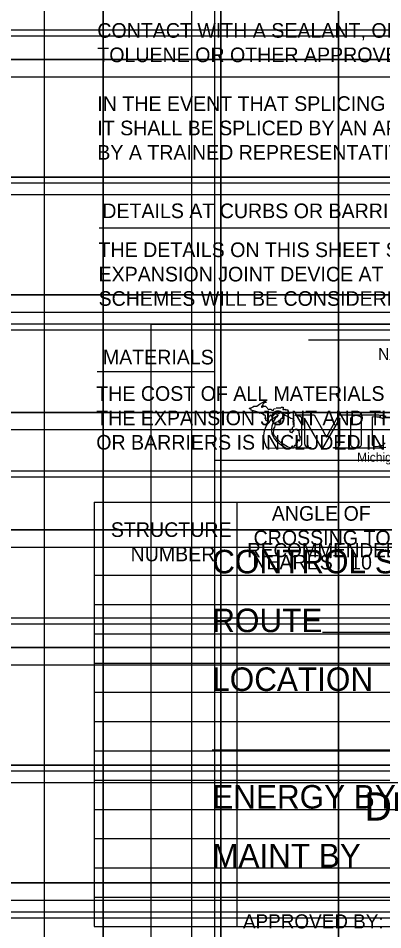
# Model space of a CAD drawing. Extents: x 19590 to 20151, y 19944 to 20103.
# Drawn here: x 20106.58 to 20118.97, y 20023.21 to 20054.22 of the extents above; entities that cross this region are included whole.
import ezdxf

# ---------------------------------------------------------------- set-up
doc = ezdxf.new("R2010")
doc.units = 0
for name, color, linetype in [('DETAIL_TEXT_DIMEN_PR', 7, 'Continuous'), ('Sheet_Border_Block_LightingInventory', 7, 'Continuous'), ('Sheet_Border_PlanOverProf_Grid+Sta+EL_40x', 7, 'Continuous'), ('Sheet_Border_PlanOverProf_Grid+Sta+EL_50x', 7, 'Continuous'), ('Sheet_Border_Prof_Triple_Grid+Sta+EL_40x', 7, 'Continuous'), ('Sheet_Border_Prof_Triple_Grid+Sta+EL_50x', 7, 'Continuous'), ('Sheet_Border_TitleSheet', 7, 'Continuous'), ('Sheet_Border_TitleSheet_ConsultantBlock', 7, 'Continuous'), ('Sheet_Border_XS_Grid', 7, 'Continuous')]:
    doc.layers.add(name, color=color, linetype=linetype)

msp = doc.modelspace()

# ---------------------------------------------------------------- linework, layer by layer
at = {"layer": 'DETAIL_TEXT_DIMEN_PR'}
for p, q in [((20109.339, 20047.087), (20121.031, 20047.087)), ((20109.261, 20042.198), (20113.23, 20042.198)), ((20109.159, 20037.759), (20109.159, 20023.328)), ((20109.159, 20037.759), (20139.598, 20037.759)), ((20114.011, 20037.759), (20114.011, 20035.271)), ((20109.159, 20035.271), (20139.598, 20035.271)), ((20114.011, 20035.271), (20114.011, 20023.348)), ((20109.159, 20034.275), (20139.598, 20034.275)), ((20109.159, 20033.28), (20139.598, 20033.28)), ((20109.159, 20032.285), (20139.598, 20032.285)), ((20109.159, 20031.29), (20139.598, 20031.29)), ((20109.159, 20030.294), (20139.598, 20030.294)), ((20109.159, 20029.299), (20139.598, 20029.299)), ((20109.159, 20028.304), (20139.598, 20028.304)), ((20109.159, 20027.309), (20139.598, 20027.309)), ((20109.159, 20026.314), (20139.598, 20026.314)), ((20109.159, 20025.318), (20139.598, 20025.318)), ((20109.159, 20024.323), (20139.598, 20024.323)), ((20109.159, 20023.328), (20139.598, 20023.328))]:
    msp.add_line(p, q, dxfattribs=at)
at = {"layer": 'Sheet_Border_Block_LightingInventory'}
for p, q in [((20111.107, 20015.013), (20111.107, 20043.813)), ((20111.107, 20043.813), (20143.267, 20043.813)), ((20116.927, 20033.337), (20140.777, 20033.337)), ((20113.177, 20029.337), (20140.777, 20029.337))]:
    msp.add_line(p, q, dxfattribs=at)
for points in [[(20115.345, 20040.961), (20115.504, 20040.961), (20115.532, 20040.99), (20115.59, 20040.99), (20115.59, 20040.961), (20115.576, 20040.904), (20115.633, 20040.904), (20115.648, 20040.918), (20115.662, 20040.904), (20115.676, 20040.904), (20115.676, 20040.889), (20115.72, 20040.904), (20115.748, 20040.875), (20115.748, 20040.832), (20115.763, 20040.832), (20115.792, 20040.803), (20115.792, 20040.788), (20115.82, 20040.788), (20115.82, 20040.774), (20115.691, 20040.774), (20115.662, 20040.788), (20115.648, 20040.788), (20115.633, 20040.76), (20115.648, 20040.745), (20115.633, 20040.731), (20115.619, 20040.731), (20115.604, 20040.76), (20115.59, 20040.774), (20115.518, 20040.788), (20115.475, 20040.803), (20115.46, 20040.788), (20115.446, 20040.76), (20115.374, 20040.745), (20115.345, 20040.76), (20115.316, 20040.76), (20115.273, 20040.731), (20115.244, 20040.688), (20115.23, 20040.688), (20115.23, 20040.702), (20115.244, 20040.716), (20115.259, 20040.745), (20115.23, 20040.731), (20115.216, 20040.731), (20115.201, 20040.716), (20115.172, 20040.688), (20115.158, 20040.731), (20115.144, 20040.702), (20115.115, 20040.673), (20115.086, 20040.63), (20115.028, 20040.529), (20115.014, 20040.529), (20115, 20040.544), (20115, 20040.572), (20115.014, 20040.616), (20115, 20040.616), (20114.985, 20040.601), (20114.971, 20040.616), (20114.985, 20040.63), (20114.985, 20040.702), (20114.971, 20040.716), (20114.928, 20040.716), (20114.928, 20040.731), (20114.913, 20040.745), (20114.928, 20040.745), (20114.913, 20040.76), (20114.884, 20040.76), (20114.856, 20040.774), (20114.827, 20040.803), (20114.812, 20040.774), (20114.784, 20040.803), (20114.769, 20040.803), (20114.74, 20040.817), (20114.654, 20040.846), (20114.496, 20040.889), (20114.496, 20040.904), (20114.467, 20040.932), (20114.467, 20040.947), (20114.438, 20040.947), (20114.582, 20041.004), (20114.582, 20041.019), (20114.697, 20041.019), (20114.74, 20041.062), (20114.784, 20041.091), (20114.884, 20041.148), (20114.942, 20041.177), (20115, 20041.177), (20115.014, 20041.163), (20115, 20041.148), (20114.985, 20041.148), (20114.956, 20041.134), (20114.928, 20041.12), (20114.913, 20041.105), (20114.884, 20041.062), (20114.87, 20041.033), (20114.856, 20041.019), (20114.856, 20040.99), (20114.87, 20040.99), (20114.884, 20041.004), (20114.899, 20041.033), (20114.928, 20041.033), (20114.899, 20041.004)], [(20114.899, 20041.004), (20114.942, 20041.019), (20114.985, 20041.019), (20115.014, 20041.004), (20115.043, 20040.961), (20115.057, 20040.947), (20115.086, 20040.904), (20115.129, 20040.918), (20115.172, 20040.918), (20115.201, 20040.889), (20115.244, 20040.875), (20115.259, 20040.889), (20115.259, 20040.904), (20115.273, 20040.932), (20115.331, 20040.947)], [(20115.921, 20040.529), (20115.921, 20040.5), (20115.921, 20040.486), (20115.95, 20040.472), (20115.95, 20040.342), (20115.936, 20040.313), (20115.921, 20040.313), (20115.907, 20040.299), (20115.892, 20040.27), (20115.892, 20040.241), (20115.878, 20040.227), (20115.835, 20040.227), (20115.82, 20040.212), (20115.82, 20040.155), (20115.835, 20040.14), (20115.878, 20040.126), (20115.907, 20040.126), (20115.907, 20040.169), (20115.921, 20040.169), (20115.95, 20040.198), (20115.95, 20040.212), (20115.936, 20040.212), (20115.993, 20040.227), (20116.036, 20040.256), (20116.065, 20040.241), (20116.08, 20040.212), (20116.123, 20040.198), (20116.123, 20040.126), (20116.137, 20040.097), (20116.137, 20040.025), (20116.166, 20039.968), (20116.166, 20039.953), (20116.152, 20039.953), (20116.152, 20039.881), (20116.123, 20039.838), (20116.108, 20039.881), (20116.094, 20039.881), (20116.08, 20039.867), (20116.08, 20039.838), (20116.065, 20039.809), (20116.065, 20039.78), (20116.022, 20039.78), (20116.022, 20039.737), (20116.008, 20039.694), (20115.993, 20039.68), (20115.979, 20039.68), (20115.964, 20039.651), (20115.95, 20039.636), (20115.95, 20039.593), (20115.878, 20039.593), (20115.82, 20039.608), (20115.734, 20039.636), (20115.532, 20039.766), (20115.432, 20039.852), (20115.374, 20039.896), (20115.345, 20039.953), (20115.302, 20039.996), (20115.273, 20040.054), (20115.259, 20040.097), (20115.259, 20040.14), (20115.273, 20040.184), (20115.273, 20040.212), (20115.259, 20040.256), (20115.288, 20040.27), (20115.302, 20040.313), (20115.331, 20040.4), (20115.316, 20040.414), (20115.331, 20040.428), (20115.345, 20040.472), (20115.36, 20040.486), (20115.403, 20040.5), (20115.417, 20040.486), (20115.432, 20040.529), (20115.46, 20040.558), (20115.446, 20040.5), (20115.446, 20040.457), (20115.475, 20040.486), (20115.489, 20040.486), (20115.46, 20040.443), (20115.489, 20040.472), (20115.504, 20040.5), (20115.504, 20040.587), (20115.518, 20040.601), (20115.532, 20040.601), (20115.547, 20040.616), (20115.604, 20040.616), (20115.604, 20040.616), (20115.576, 20040.616), (20115.561, 20040.644), (20115.576, 20040.673), (20115.576, 20040.702), (20115.59, 20040.716), (20115.648, 20040.716), (20115.676, 20040.702), (20115.72, 20040.688), (20115.734, 20040.688), (20115.763, 20040.673), (20115.777, 20040.659), (20115.849, 20040.616), (20115.936, 20040.587), (20115.95, 20040.515)], [(20115.95, 20040.515), (20115.936, 20040.529)], [(20118.988, 20040.587), (20118.945, 20040.616), (20118.888, 20040.63), (20118.888, 20040.716), (20118.96, 20040.716), (20119.075, 20040.688)], [(20119.075, 20039.622), (20118.931, 20039.593), (20118.888, 20039.593), (20118.888, 20039.68), (20118.916, 20039.68), (20118.974, 20039.694), (20119.06, 20039.78)]]:
    msp.add_lwpolyline(points, dxfattribs=at)
for points in [[(20116.641, 20040.731), (20117.059, 20039.968), (20117.476, 20040.731), (20118.096, 20040.731), (20118.096, 20040.702), (20118.052, 20040.702), (20117.937, 20040.673), (20117.923, 20040.673), (20117.923, 20040.659), (20117.894, 20040.63), (20117.88, 20040.601), (20117.88, 20039.708), (20117.894, 20039.68), (20117.937, 20039.636), (20117.995, 20039.622), (20118.096, 20039.622), (20118.096, 20039.593), (20117.304, 20039.593), (20117.304, 20039.622), (20117.419, 20039.622), (20117.462, 20039.636), (20117.476, 20039.665), (20117.505, 20039.68), (20117.52, 20039.708), (20117.52, 20040.616), (20116.929, 20039.593), (20116.9, 20039.593), (20116.31, 20040.616), (20116.31, 20039.752), (20116.339, 20039.68), (20116.382, 20039.651), (20116.44, 20039.622), (20116.526, 20039.622), (20116.526, 20039.593), (20116.008, 20039.593), (20116.008, 20039.622), (20116.022, 20039.622), (20116.123, 20039.636), (20116.166, 20039.651), (20116.18, 20039.665), (20116.209, 20039.694), (20116.224, 20039.723), (20116.224, 20040.601), (20116.209, 20040.63), (20116.195, 20040.659), (20116.166, 20040.673), (20116.123, 20040.688), (20116.051, 20040.702), (20116.008, 20040.702), (20116.008, 20040.731)], [(20118.844, 20040.644), (20118.772, 20040.644), (20118.614, 20040.659), (20118.614, 20039.708), (20118.628, 20039.694), (20118.657, 20039.665), (20118.744, 20039.651), (20118.83, 20039.665), (20118.888, 20039.68), (20118.888, 20039.593), (20118.038, 20039.593), (20118.038, 20039.622), (20118.139, 20039.622), (20118.182, 20039.636), (20118.225, 20039.665), (20118.24, 20039.68), (20118.254, 20039.708), (20118.254, 20040.601), (20118.24, 20040.63), (20118.225, 20040.659), (20118.096, 20040.702), (20118.038, 20040.702), (20118.038, 20040.731), (20118.844, 20040.731), (20118.888, 20040.716), (20118.888, 20040.63)], [(20115.057, 20039.593), (20115.014, 20039.651), (20114.985, 20039.723), (20114.956, 20039.795), (20114.928, 20039.953), (20114.928, 20040.025), (20114.956, 20040.184), (20115.014, 20040.342), (20115.057, 20040.414), (20115.115, 20040.472), (20115.172, 20040.558), (20115.244, 20040.616), (20115.417, 20040.716), (20115.36, 20040.644), (20115.316, 20040.601), (20115.288, 20040.544), (20115.244, 20040.472), (20115.23, 20040.414), (20115.201, 20040.342), (20115.187, 20040.256), (20115.187, 20040.169), (20115.201, 20040.097), (20115.244, 20039.996), (20115.288, 20039.924), (20115.36, 20039.838), (20115.46, 20039.752), (20115.576, 20039.665), (20115.72, 20039.579)]]:
    msp.add_lwpolyline(points, close=True, dxfattribs=at)
at = {"layer": 'Sheet_Border_PlanOverProf_Grid+Sta+EL_40x'}
for p, q in [((20137.467, 20053.813), (20017.467, 20053.813)), ((20107.467, 20053.813), (20107.467, 20016.413)), ((20112.467, 20053.813), (20112.467, 20016.413)), ((20117.467, 20053.813), (20117.467, 20016.413)), ((20137.467, 20048.813), (20017.467, 20048.813)), ((20137.467, 20043.813), (20017.467, 20043.813)), ((20137.467, 20038.813), (20017.467, 20038.813)), ((20137.467, 20033.813), (20017.467, 20033.813)), ((20137.467, 20028.813), (20017.467, 20028.813)), ((20137.467, 20023.813), (20017.467, 20023.813))]:
    msp.add_line(p, q, dxfattribs=at)
at = {"layer": 'Sheet_Border_PlanOverProf_Grid+Sta+EL_50x'}
for p, q in [((20137.467, 20052.813), (20017.467, 20052.813)), ((20109.467, 20052.813), (20109.467, 20018.413)), ((20113.467, 20052.813), (20113.467, 20018.413)), ((20117.467, 20052.813), (20117.467, 20018.413)), ((20137.467, 20048.813), (20017.467, 20048.813)), ((20137.467, 20044.813), (20017.467, 20044.813)), ((20137.467, 20040.813), (20017.467, 20040.813)), ((20137.467, 20036.813), (20017.467, 20036.813)), ((20137.467, 20032.813), (20017.467, 20032.813)), ((20137.467, 20028.813), (20017.467, 20028.813)), ((20137.467, 20024.813), (20017.467, 20024.813))]:
    msp.add_line(p, q, dxfattribs=at)
at = {"layer": 'Sheet_Border_Prof_Triple_Grid+Sta+EL_40x'}
for p, q in [((20107.467, 20093.613), (20107.467, 20016.213)), ((20112.467, 20093.613), (20112.467, 20016.213)), ((20117.467, 20093.613), (20117.467, 20016.213)), ((20137.467, 20053.613), (20017.467, 20053.613)), ((20137.467, 20048.613), (20017.467, 20048.613)), ((20137.467, 20043.613), (20017.467, 20043.613)), ((20137.467, 20038.613), (20017.467, 20038.613)), ((20137.467, 20033.613), (20017.467, 20033.613)), ((20137.467, 20028.613), (20017.467, 20028.613)), ((20137.467, 20023.613), (20017.467, 20023.613))]:
    msp.add_line(p, q, dxfattribs=at)
at = {"layer": 'Sheet_Border_Prof_Triple_Grid+Sta+EL_50x'}
for p, q in [((20109.467, 20092.213), (20109.467, 20017.813)), ((20113.467, 20092.213), (20113.467, 20017.813)), ((20117.467, 20092.213), (20117.467, 20017.813)), ((20137.467, 20052.213), (20017.467, 20052.213)), ((20137.467, 20048.213), (20017.467, 20048.213)), ((20137.467, 20044.213), (20017.467, 20044.213)), ((20137.467, 20040.213), (20017.467, 20040.213)), ((20137.467, 20036.213), (20017.467, 20036.213)), ((20137.467, 20032.213), (20017.467, 20032.213)), ((20137.467, 20028.213), (20017.467, 20028.213)), ((20137.467, 20024.213), (20017.467, 20024.213))]:
    msp.add_line(p, q, dxfattribs=at)
at = {"layer": 'Sheet_Border_TitleSheet'}
for p, q in [((20113.267, 20039.191), (20143.267, 20039.191)), ((20113.267, 20015.013), (20113.267, 20039.191))]:
    msp.add_line(p, q, dxfattribs=at)
at = {"layer": 'Sheet_Border_TitleSheet_ConsultantBlock'}
for p, q in [((20113.267, 20039.191), (20113.267, 20069.191)), ((20116.451, 20043.277), (20133.042, 20043.277))]:
    msp.add_line(p, q, dxfattribs=at)
at = {"layer": 'Sheet_Border_XS_Grid'}
for p, q in [((20109.467, 20016.813), (20109.467, 20092.813)), ((20113.467, 20016.813), (20113.467, 20092.813)), ((20117.467, 20016.813), (20117.467, 20092.813)), ((20013.467, 20052.813), (20141.467, 20052.813)), ((20013.467, 20048.813), (20141.467, 20048.813)), ((20013.467, 20044.813), (20141.467, 20044.813)), ((20013.467, 20040.813), (20141.467, 20040.813)), ((20013.467, 20036.813), (20141.467, 20036.813)), ((20013.467, 20032.813), (20141.467, 20032.813)), ((20013.467, 20028.813), (20141.467, 20028.813)), ((20013.467, 20024.813), (20141.467, 20024.813))]:
    msp.add_line(p, q, dxfattribs=at)

# ---------------------------------------------------------------- texts
at = {"layer": 'DETAIL_TEXT_DIMEN_PR'}
for s, height, p in [('CONTACT WITH A SEALANT, OR LUBRICANT-ADHESIVE SHALL BE CLEANED WITH ', 0.49762, (20109.271, 20053.554)), ('TOLUENE OR OTHER APPROVED SOLVENT.', 0.49762, (20109.271, 20052.724)), ('DETAILS AT CURBS OR BARRIERS', 0.49762, (20109.44, 20047.418)), ('THE DETAILS ON THIS SHEET SHOW AN APPROVED MEANS OF TERMINATING THE', 0.49762, (20109.313, 20046.094)), ('EXPANSION JOINT DEVICE AT CURBS OR BARRIERS.  VARIATIONS OR ALTERNATIVE', 0.49762, (20109.313, 20045.265)), ('SCHEMES WILL BE CONSIDERED AND MAY BE USED IF APPROVED BY THE ENGINEER.', 0.49762, (20109.313, 20044.436)), ('MATERIALS', 0.4976, (20109.459, 20042.443)), ('THE COST OF ALL MATERIALS AND LABOR REQUIRED FOR PROPER INSTALLATION OF', 0.49762, (20109.235, 20041.204)), ('THE EXPANSION JOINT AND THE TERMINAL ASSEMBLIES AT THE CURBS, SIDEWALKS,', 0.49762, (20109.235, 20040.375)), ('OR BARRIERS IS INCLUDED IN THE PAYMENT FOR THE EXPANSION JOINT DEVICE.', 0.49762, (20109.235, 20039.546)), ('ANGLE OF', 0.4976, (20115.202, 20037.127)), ('STRUCTURE', 0.4976, (20109.731, 20036.575)), ('CROSSING TO', 0.49762, (20114.583, 20036.298)), ('NUMBER', 0.4976, (20110.401, 20035.746)), ('NEAREST 10', 0.4976, (20114.539, 20035.468))]:
    msp.add_text(s, height=height, rotation=0, dxfattribs=at).set_placement(p)
for s, p in [('IN THE EVENT THAT SPLICING IS REQUIRED OF THE SEALING GLAND,', (20109.271, 20051.066)), ('IT SHALL BE SPLICED BY AN APPROVED METHOD (SUCH AS COLD VULCANIZATION)', (20109.271, 20050.236)), ('BY A TRAINED REPRESENTATIVE OF THE MANUFACTURER.', (20109.271, 20049.407))]:
    msp.add_text(s, height=0.49762, dxfattribs=at).set_placement(p)
at = {"layer": 'Sheet_Border_Block_LightingInventory'}
msp.add_text('Michigan Department of Transportation', height=0.30492, rotation=360, dxfattribs=at).set_placement((20118.103, 20039.133))
for s, height, p in [('CONTROL SEC', 0.79996, (20113.177, 20035.337)), ('ROUTE', 0.8, (20113.177, 20033.337)), ('LOCATION', 0.8, (20113.177, 20031.337)), ('ENERGY BY', 0.8, (20113.177, 20027.337)), ('MAINT BY', 0.8, (20113.177, 20025.337))]:
    msp.add_text(s, height=height, dxfattribs=at).set_placement(p)
at = {"layer": 'Sheet_Border_TitleSheet'}
for s, height, p in [('RECOMMENDED FOR APPROVAL BY:', 0.48, (20114.368, 20035.887)), ('DEPARTMENT OF TRANSPORTATION', 0.96, (20118.358, 20026.928)), ('APPROVED BY:', 0.48, (20114.223, 20023.259))]:
    msp.add_text(s, height=height, dxfattribs=at).set_placement(p)
at = {"layer": 'Sheet_Border_TitleSheet_ConsultantBlock'}
msp.add_text('                NAME, P.E.  -  TITLE               ', height=0.4, dxfattribs=at).set_placement((20116.437, 20042.597))

doc.saveas('drawing.dxf')
